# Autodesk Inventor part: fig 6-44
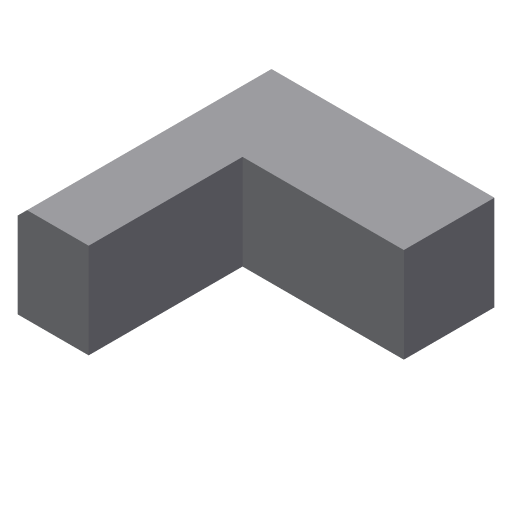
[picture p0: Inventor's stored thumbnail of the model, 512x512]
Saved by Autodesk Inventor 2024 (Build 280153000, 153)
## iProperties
Created: 2010-08
Part Number: fig 6-44
Document SubType Name: Modeling
Designer: CADSoft
Density: 1 g/cm^3
Material: Generic
Appearance: Default
Author: CADSoft
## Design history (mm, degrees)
sketch "Sketch1"
  geometry: L1 (-33.983, 0)-(-48.97, 0); L2 (-48.97, 0)-(-48.97, 51.503); L3 (-48.97, 51.503)-(0, 51.503); L4 (0, 51.503)-(0, 32.411); L5 (-33.983, 0)-(-33.983, 32.411); L6 (-33.983, 32.411)-(0, 32.411); 1 further point
  constraints: 12 end point, 3 parallel, 2 perpendicular, 1 horizontal
extrude "Extrusion1" new body sketch "Sketch1" distance "d0" = 20; taper "d1" = 0 deg
chamfer "Chamfer1" distance "d2" = 2; stored, may be unused: second distance "d3" = 2, angle "d4" = 45 deg
body "Solid1"
